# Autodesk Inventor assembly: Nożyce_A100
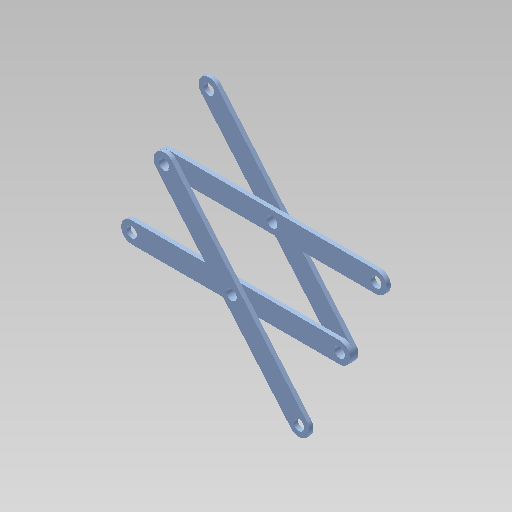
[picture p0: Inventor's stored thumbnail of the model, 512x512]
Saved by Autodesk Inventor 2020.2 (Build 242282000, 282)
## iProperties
Created: 2006-06
Part Number: Nożyce_A100
Document SubType Name: Assembly
Designer: F.Stasiak
Manager: www.cadconsulting.pl
Company: Fabian Stasiak CAD Consulting
Author: F.Stasiak
Subject: Zbiór ćwiczeń. Autodesk Inventor 2020. Kurs podstawowy
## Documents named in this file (2)
- C:\2020_Kurs_podstawowy\R6 Zespoły\Adaptacyjność\Nożyce_A100.iam
- C:\2020_Kurs_podstawowy\R6 Zespoły\Adaptacyjność\Belka_A100.ipt
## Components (4 placed, 1 different names)
1. Belka_A100:1 — Wstaw:1, Wstaw:2, Zestawiający:1, Kąt:1
2. Belka_A100:2 — Wstaw:1, Wstaw:3, Kąt:1
3. Belka_A100:3 — Wstaw:3, Wstaw:4, Zestawiający:1
4. Belka_A100:4 — Wstaw:2, Wstaw:4
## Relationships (6: Insert 4, Mate 1, Angle 1)
- Wstaw:1 [Insert]: Belka_A100:1 ↔ Belka_A100:2
- Wstaw:2 [Insert]: Belka_A100:1 ↔ Belka_A100:4
- Wstaw:3 [Insert]: Belka_A100:2 ↔ Belka_A100:3
- Wstaw:4 [Insert]: Belka_A100:3 ↔ Belka_A100:4
- Zestawiający:1 [Mate]: Belka_A100:1 ↔ Belka_A100:3
- Kąt:1 [Angle]: Belka_A100:1 ↔ Belka_A100:2
